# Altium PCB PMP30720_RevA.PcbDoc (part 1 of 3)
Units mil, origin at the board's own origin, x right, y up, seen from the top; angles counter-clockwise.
Board outline 4575 x 5400 mil, 4 copper layers (Top Layer, Signal Layer 1, Signal Layer 2, Bottom Layer), stack 61.6 mil thick; 223 components, 107 nets, 514 pads, 63 vias.
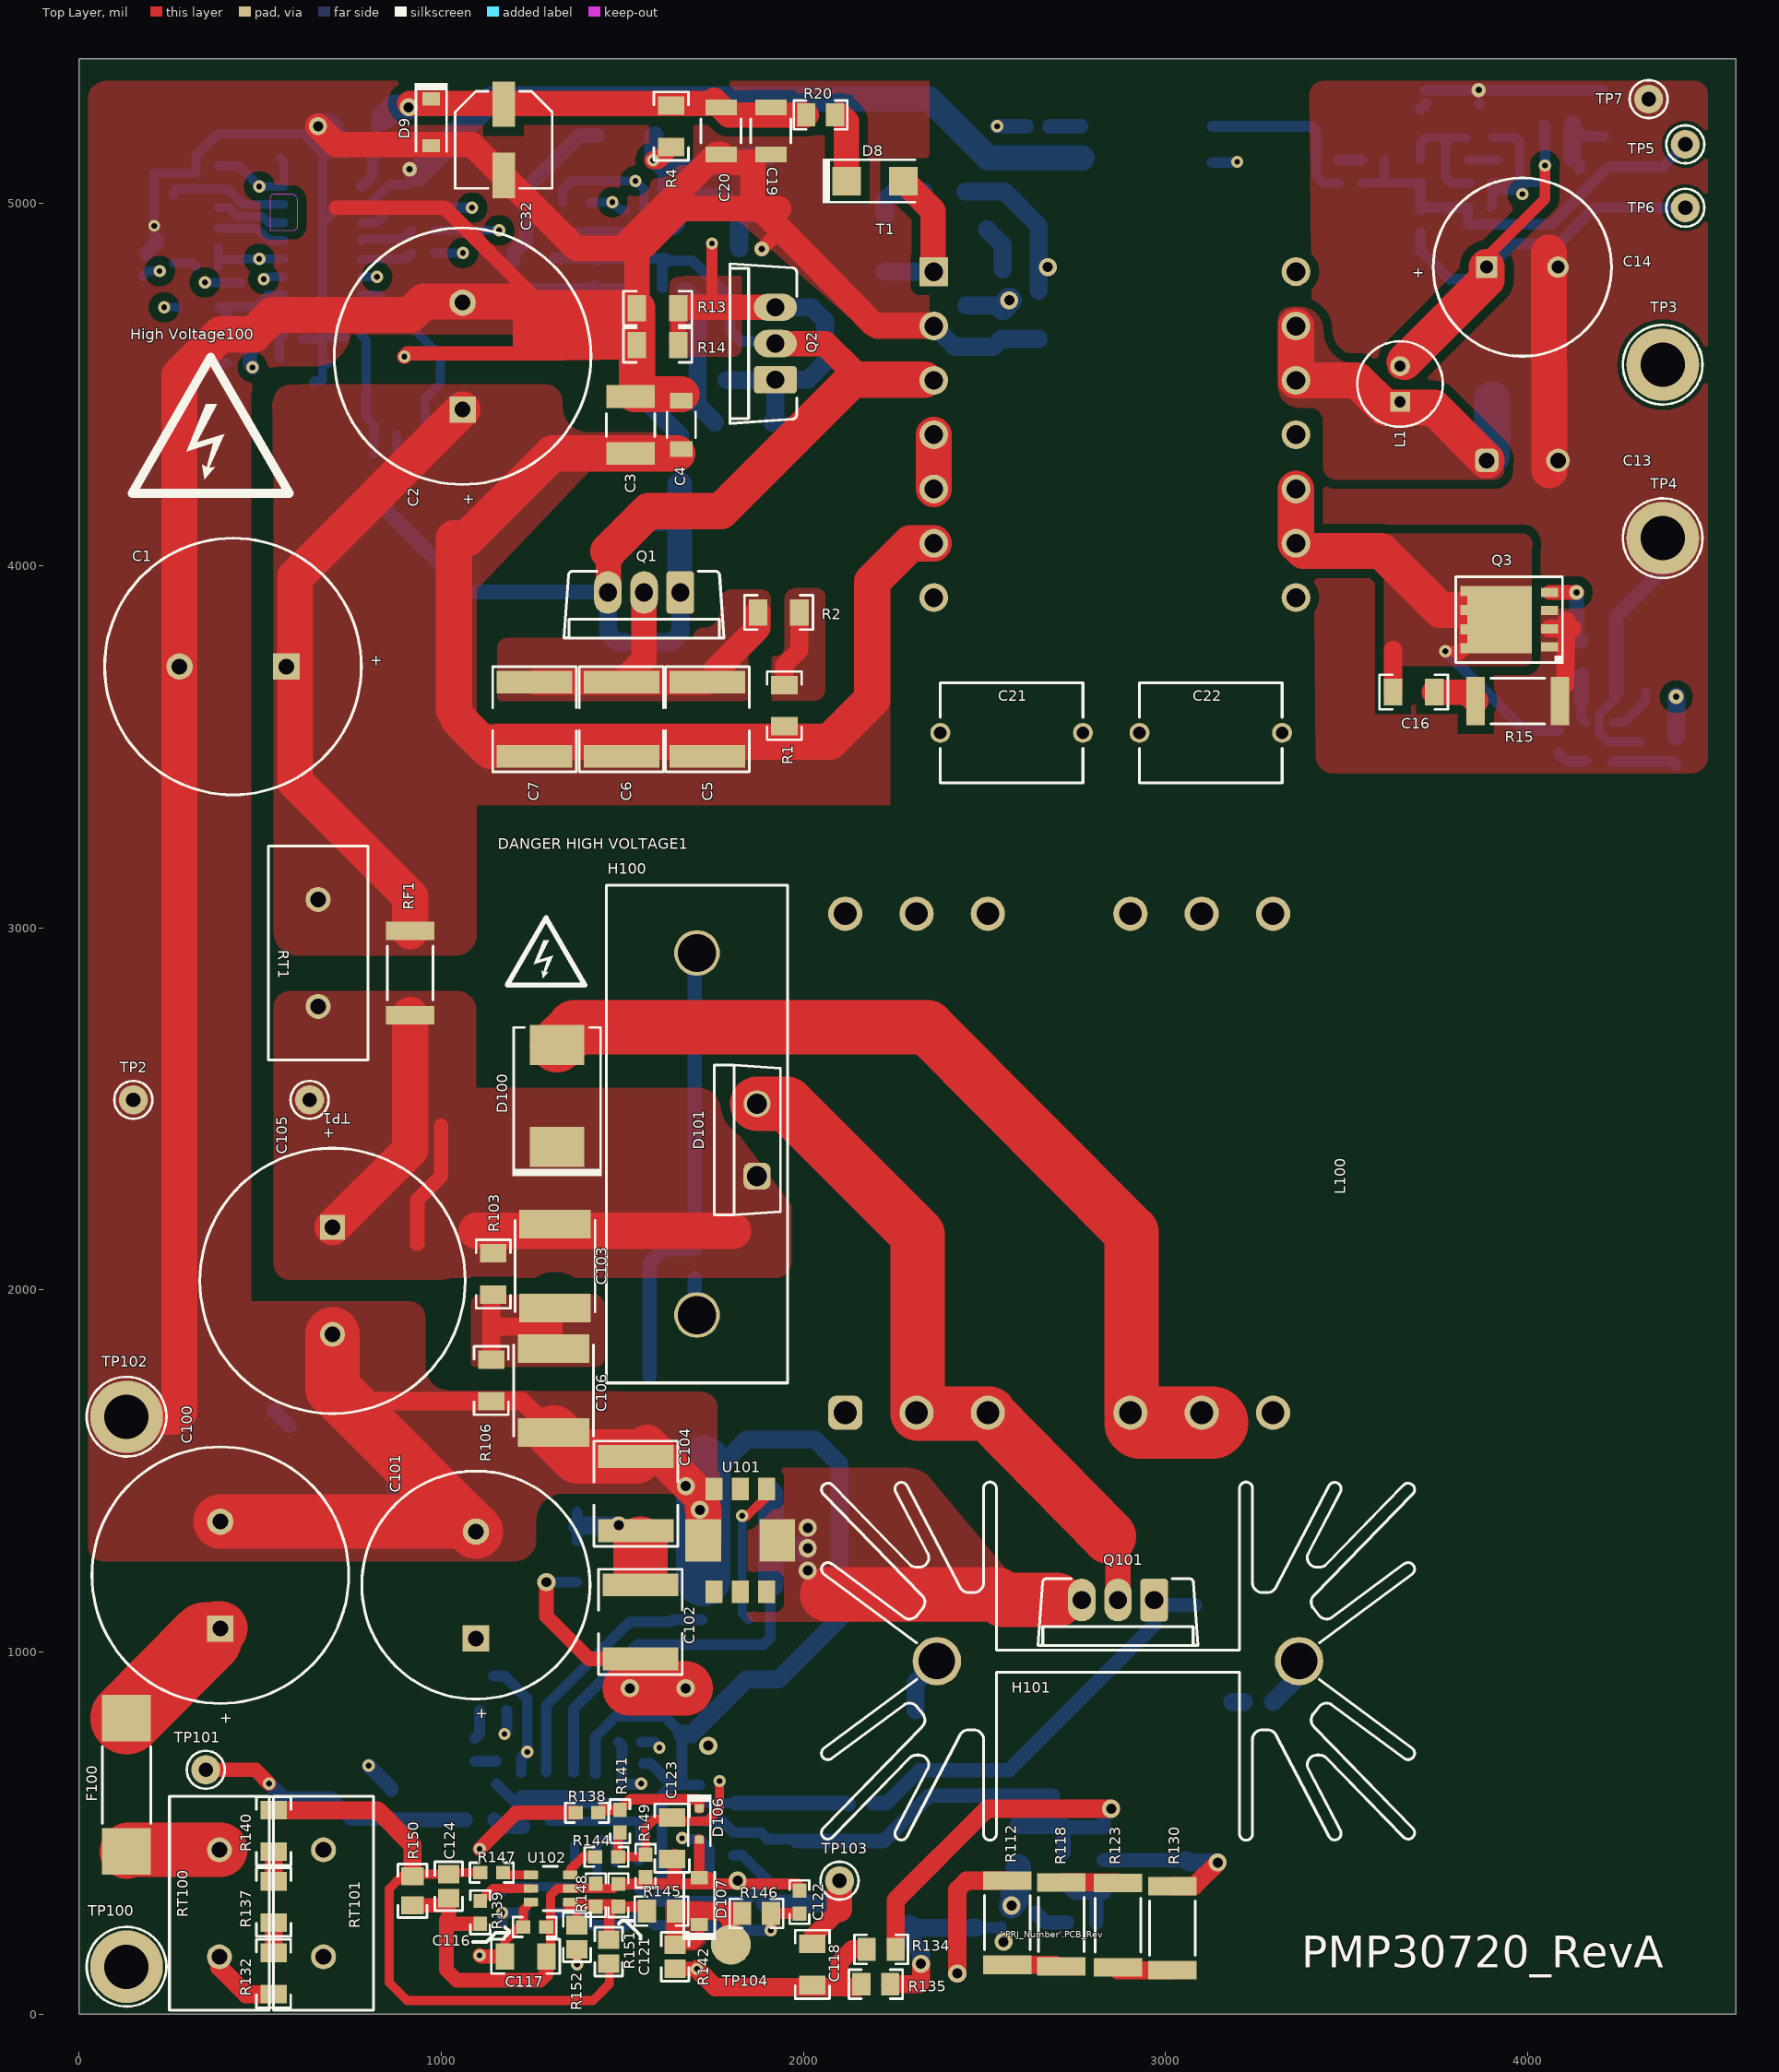
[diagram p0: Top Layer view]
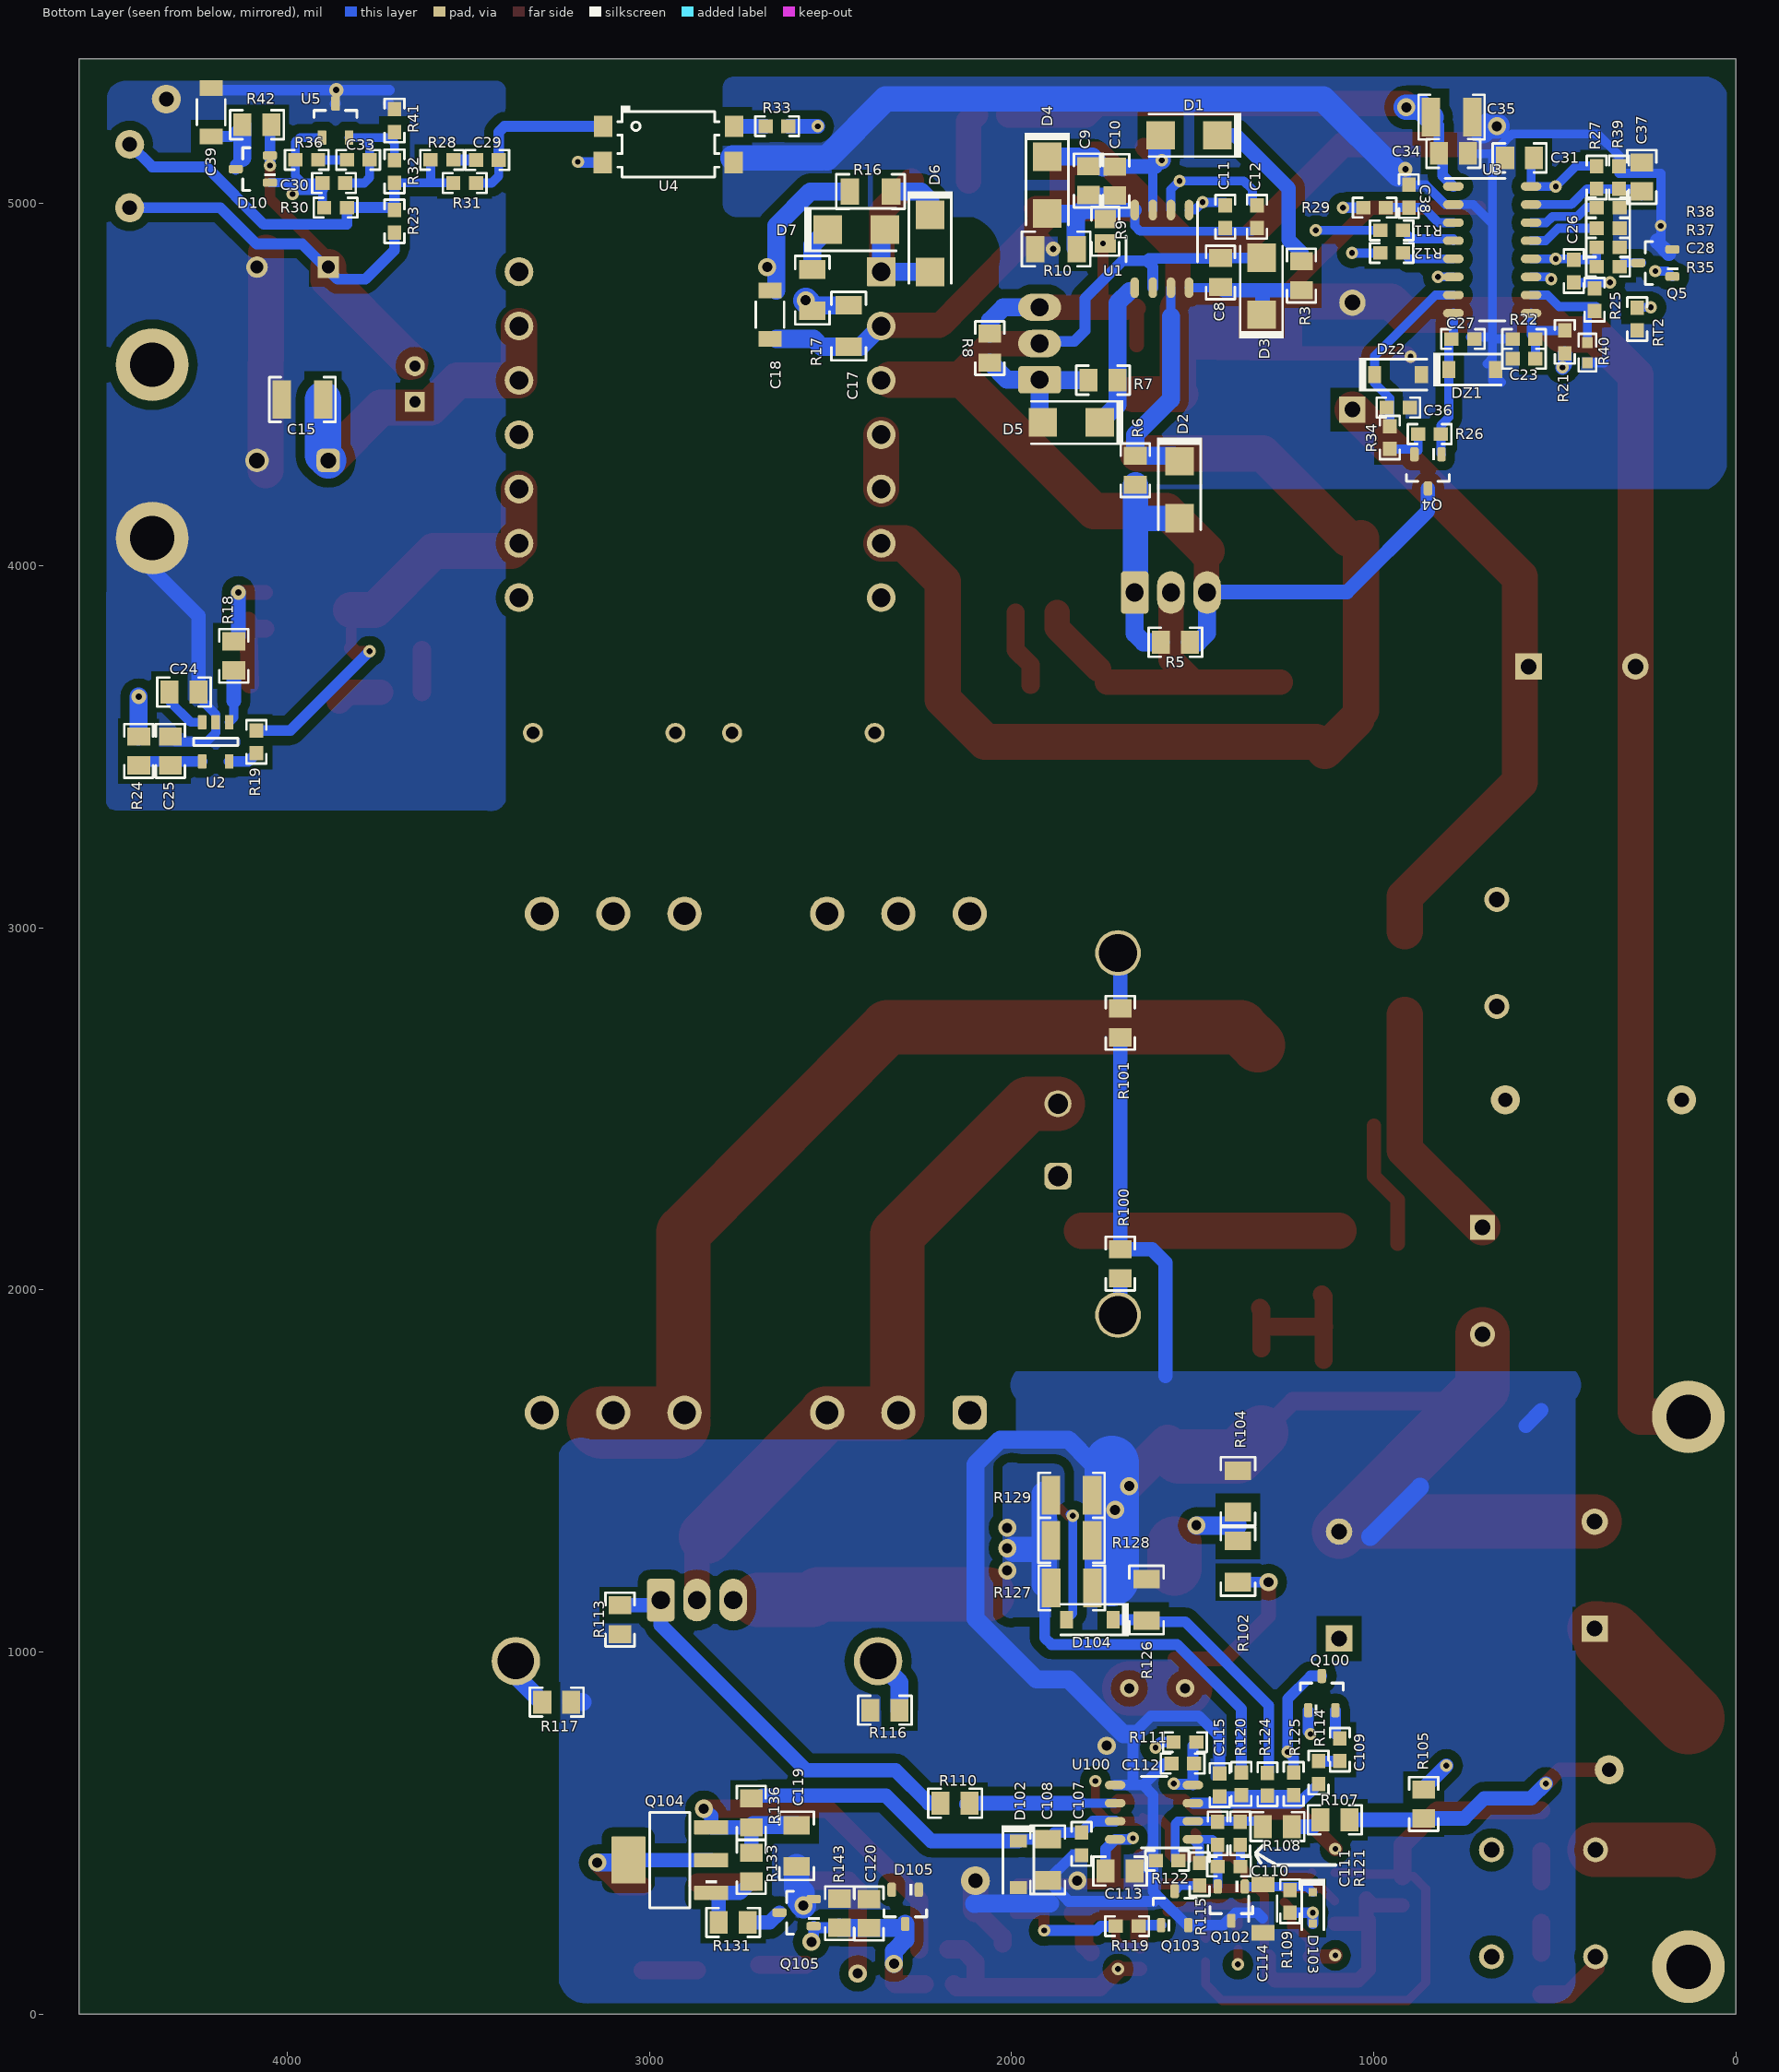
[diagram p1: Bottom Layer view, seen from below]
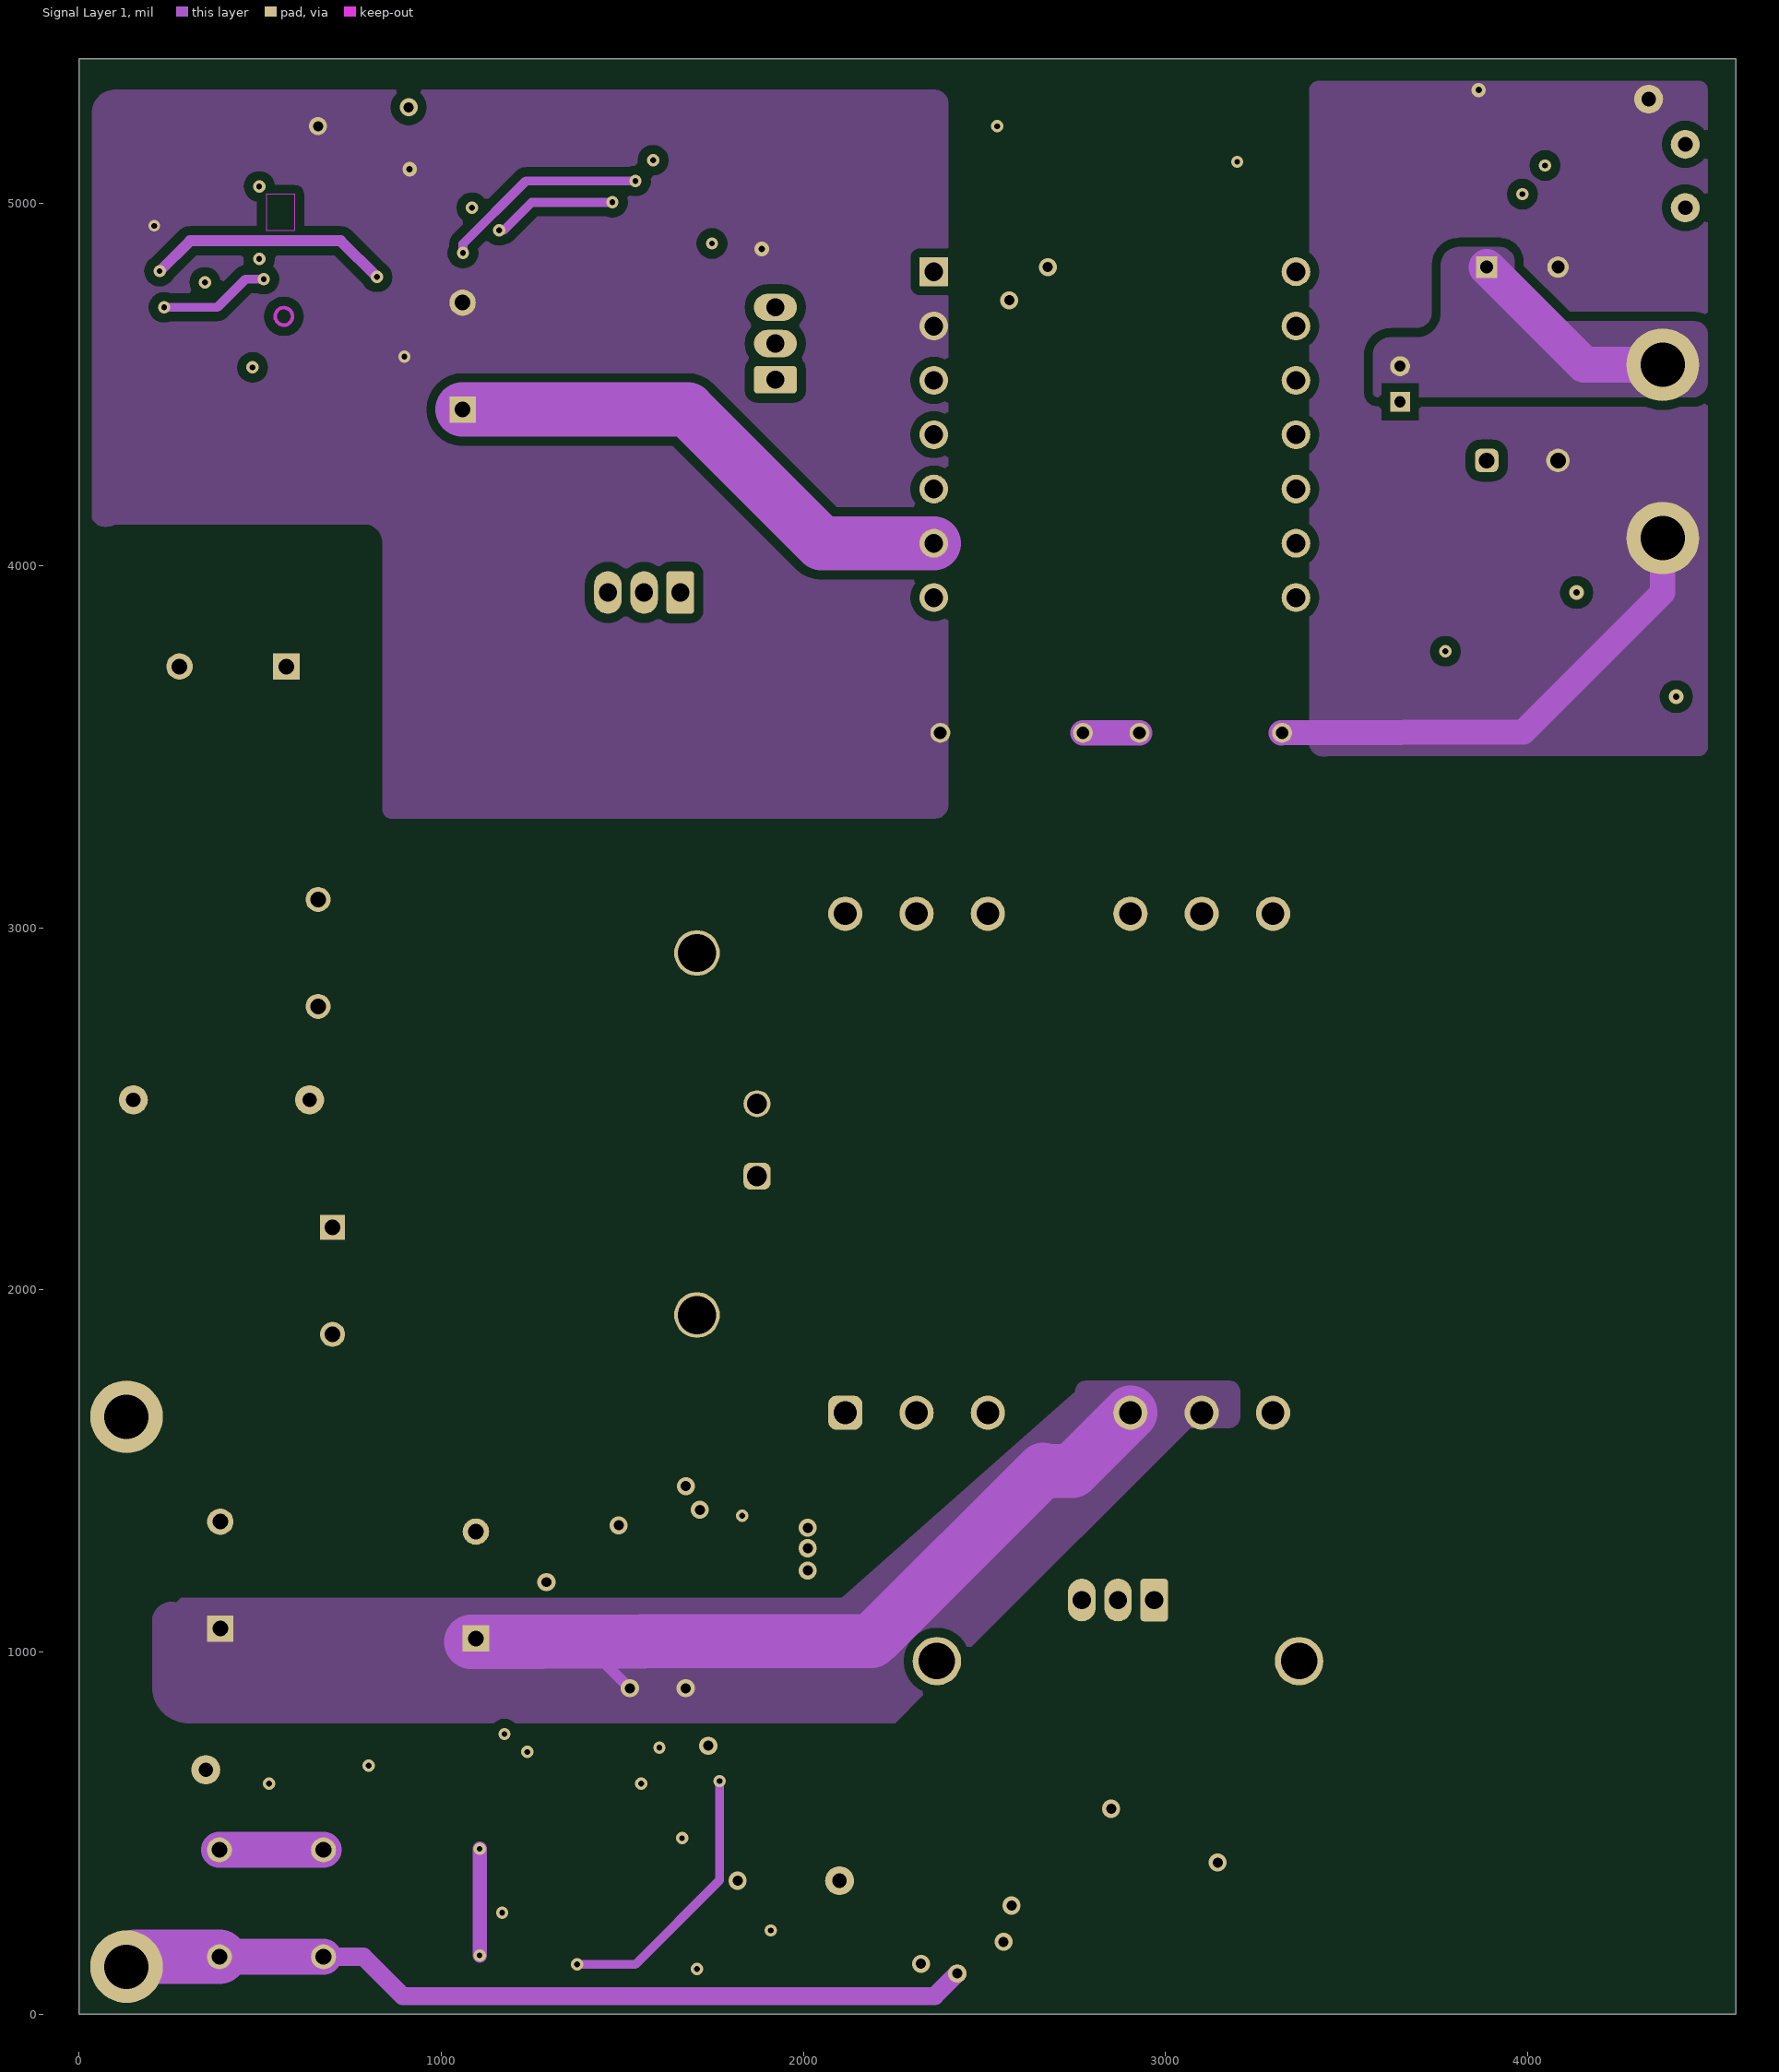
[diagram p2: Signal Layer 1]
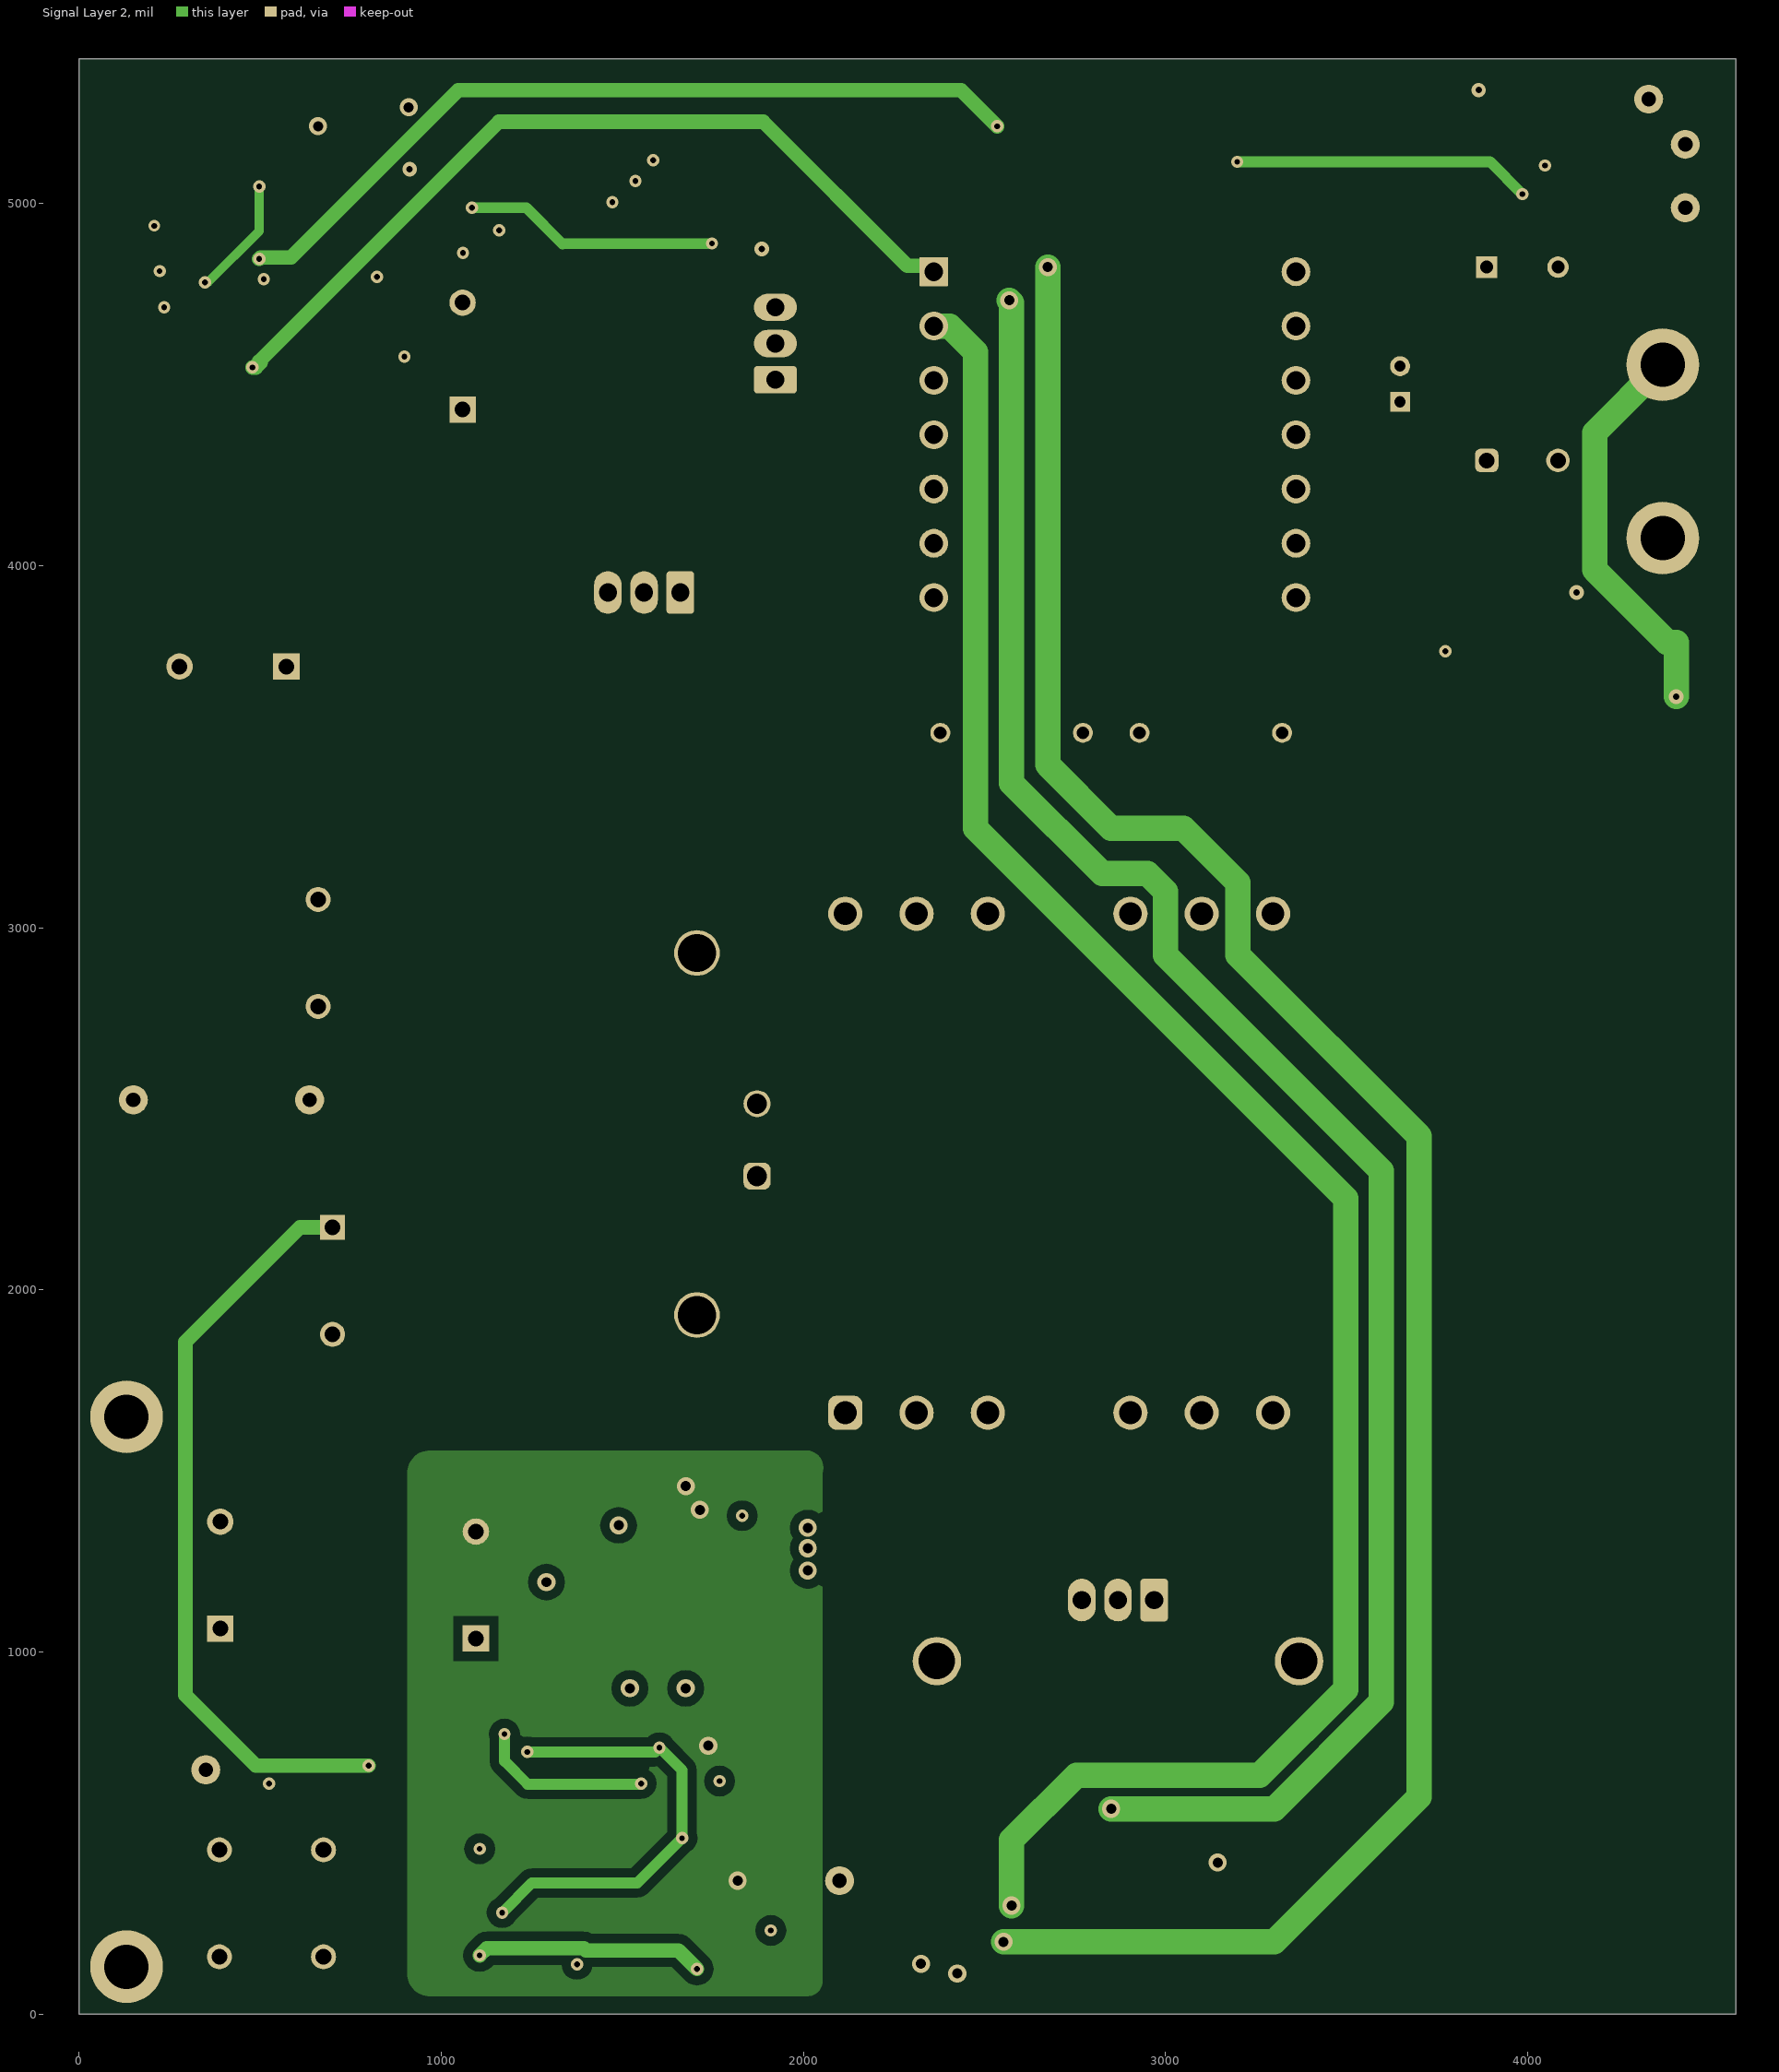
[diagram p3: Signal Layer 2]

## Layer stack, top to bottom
Top Solder: solder mask 0.4, Solder Resist, Dk 3.5
Top Layer: signal copper 1.4
Dielectric1: prepreg 8, FR-4, Dk 4.2
Signal Layer 1: signal copper 1.4
Dielectric 2: core 40, FR-4, Dk 4.2
Signal Layer 2: signal copper 1.4
Dielectric 3: prepreg 8, FR-4, Dk 4.2
Bottom Layer: signal copper 1.4
Bottom Solder: solder mask 0.4, Solder Resist, Dk 3.5

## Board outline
0,0 4575,0 4575,5400 0,5400

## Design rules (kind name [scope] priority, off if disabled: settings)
AcuteAngle [All] p1: minimum=4.50000000000000E+0001 checktracksonly=FALSE
AssemblyTestPointUsage [All] p1: valid=2
BoardOutlineClearance BoardOutlineClearance_MountingHoles [OnCopper and InComponentClass('Mounting Holes')] p1: gap=39.37 ignorepadtopadclearanceinfootprint=FALSE
BoardOutlineClearance BoardOutlineClearance_Poly [OnCopper and IsPoly] p2: gap=25 ignorepadtopadclearanceinfootprint=FALSE
BoardOutlineClearance [OnCopper and Not InComponentClass('Logo') and not InComponentClass('FiducialMark') and not InRegion(1000,500,4000,800) and not InPoly] p3: gap=18 ignorepadtopadclearanceinfootprint=FALSE
Clearance Clearance_Keepouts [((IsTrack Or IsArc) And Not InPoly) And IsFree and IsKeepOut vs ((IsTrack Or IsArc) And Not InPoly) And IsFree and IsKeepOut] p1: gap=0 ignorepadtopadclearanceinfootprint=FALSE
Clearance Clearance_Poly [InPolygon] p2: gap=25 ignorepadtopadclearanceinfootprint=TRUE
Clearance Clearance_FiducialMark [IsKeepOut and InComponentClass('FiducialMark') vs IsPad and InComponentClass('FiducialMark')] p3: gap=0 ignorepadtopadclearanceinfootprint=FALSE
Clearance [All] p4: gap=7.87 ignorepadtopadclearanceinfootprint=TRUE
ComponentClearance ComponentClearance_MountingHoles_FiducialMarks [InComponentClass('Mounting Holes') vs InComponentClass('FiducialMark')] p1: gap=50 collisioncheckmode=3 verticalgap=10 showdistances=FALSE
ComponentClearance ComponentClearance_Shunt [InComponentClass('Header') vs InComponentClass('Shunt')] p2: gap=0 collisioncheckmode=3 verticalgap=0 showdistances=FALSE
ComponentClearance ComponentClearance_Logo [InComponentClass('Logo')] p3: gap=50 collisioncheckmode=3 verticalgap=10 showdistances=FALSE
ComponentClearance ComponentClearance_ScrewToNut [(HasFootprint('NY PMS 440 0025 PH')) vs (HasFootprint('Keystone_1902C'))] p4: gap=5 collisioncheckmode=3 verticalgap=10 showdistances=FALSE
ComponentClearance ComponentClearance_MountingHoles [InComponentClass('Mounting Holes')] p5: gap=250 collisioncheckmode=3 verticalgap=100000 showdistances=FALSE
ComponentClearance ComponentClearance_SmallPassives [HasFootprint('0201*') or HasFootprint('0402*') or HasFootprint('0508') or HasFootprint('0603*') or HasFootprint('0612') or HasFootprint('0805*') or HasFootprint('0815*') or HasFootprint('0830*') or HasFootprint('1206*') or HasFootprint('1210*') or HasFootprint('1808*') or HasFootprint('1812*') or HasFootprint('1825*') or HasFootprint('2010*') or HasFootprint('2220*') or HasFootprint('2225*') or HasFootprint('2512*') or HasFootprint('2728*') or HasFootprint('3518*') vs HasFootprint('0201*') or HasFootprint('0402*') or HasFootprint('0508') or HasFootprint('0603*') or HasFootprint('0612') or HasFootprint('0805*') or HasFootprint('0815*') or HasFootprint('0830*') or HasFootprint('1206*') or HasFootprint('1210*') or HasFootprint('1808*') or HasFootprint('1812*') or HasFootprint('1825*') or HasFootprint('2010*') or HasFootprint('2220*') or HasFootprint('2225*') or HasFootprint('2512*') or HasFootprint('2728*') or HasFootprint('3518*')] p6: gap=14.96 collisioncheckmode=3 verticalgap=10 showdistances=FALSE
ComponentClearance ComponentClearance_THtoSMT [IsThruComponent vs IsSMTComponent] p7: gap=10 collisioncheckmode=3 verticalgap=10 showdistances=FALSE
ComponentClearance ComponentClearance_THtoTH [IsThruComponent vs IsThruComponent] p8: gap=10 collisioncheckmode=3 verticalgap=10 showdistances=FALSE
ComponentClearance [All] p9: gap=0 collisioncheckmode=3 verticalgap=0 showdistances=FALSE
DiffPairsRouting [All] p1: maxlimit=100 minlimit=10 mostfreqgap=10 toplayer_minwidth=15 toplayer_maxwidth=15 toplayer_prefwidth=15 midlayer1_minwidth=15 midlayer1_maxwidth=15 midlayer1_prefwidth=15 midlayer2_minwidth=15 midlayer2_maxwidth=15 midlayer2_prefwidth=15 bottomlayer_minwidth=15 bottomlayer_maxwidth=15 bottomlayer_prefwidth=15 maxuncoupledlength=1000
FabricationTestPointUsage TestPointUsage [All] p1: valid=2 allowmultiple=FALSE
FabricationTestpoint Testpoint [All] p1: side=3 testpointundercomponent=TRUE minsize=40 maxsize=100 preferedsize=60 minholesize=0 maxholesize=40 preferedholesize=32 testpointgrid=1 allowsidetop=TRUE allowsidebottom=TRUE usegrid=TRUE gridtolerance=0.01
FanoutControl Fanout_LCC [IsLCC] p1: bgadir=Out bgaviamode=Centered fanoutstyle=Auto fanoutdirection=Alternating viagrid=1 // Fanout_LCC (Default Rule)
FanoutControl Fanout_BGA [IsBGA] p2: bgadir=Out bgaviamode=Centered fanoutstyle=Auto fanoutdirection=Alternating viagrid=1 // Fanout_BGA (Default Rule)
FanoutControl Fanout_Default [All] p4: bgadir=Out bgaviamode=Centered fanoutstyle=Auto fanoutdirection=Alternating viagrid=1 // Fanout_Default (Default Rule)
FanoutControl Fanout_Small [(CompPinCount < 5)] p5: bgadir=Out bgaviamode=Centered fanoutstyle=Auto fanoutdirection=OutThenIn viagrid=1 // Fanout_Small (Default Rule)
Height [All] p1: minheight=0 maxheight=4000 prefheight=500
HoleSize [All] p1: absolutevalues=TRUE maxlimit=251 minlimit=7.87 maxpercent=80.000 minpercent=20.000
MinimumAnnularRing MinimumAnnularRing_ThermalPadVias [IsVia and InAnyComponent] p1: minimumring=5.91
MinimumAnnularRing [All] p2: minimumring=7.87
MinimumSolderMaskSliver MinimumSolderMaskSliver_Logo [InComponentClass('Logo') vs InComponentClass('Logo')] p1: minsoldermaskwidth=0.7
MinimumSolderMaskSliver [All] p2: minsoldermaskwidth=1
PlaneConnect [All] p1: planeconnectstyle=Relief reliefexpansion=10 reliefentries=4 reliefconductorwidth=10 reliefairgap=10
PolygonConnect [All] p1: connectstyle=Direct reliefconductorwidth=10 reliefentries=4 polygonreliefangle="90 Angle" airgapwidth=10
RoutingVias ThermalPadVias [IsVia and InAnyComponent] p1: holewidth=7.87 width=19.68 viastyle="Through Hole" minholewidth=7.87 minwidth=19.68 maxholewidth=12.99 maxwidth=23.62
RoutingVias [All] p2: holewidth=16 width=34 viastyle="Through Hole" minholewidth=7.87 minwidth=26 maxholewidth=40 maxwidth=65
SilkToBoardRegionClearance [Not ((IsComment or IsDesignator) And (Hide <> 'False')) and not InRegion(1000,500,4000,800)] p1:
SilkToSilkClearance SilkToSilkClearance_Pb-FreeLogo [(HasFootprint('Pb-Free_Overlay_Medium') OR HasFootprint('Pb-Free_Overlay_Small')) vs (HasFootprint('Pb-Free_Overlay_Medium') OR HasFootprint('Pb-Free_Overlay_Small'))] p1 off: silktosilkclearance=0
SilkToSilkClearance [All] p2 off: silktosilkclearance=3.94
SilkToSolderMaskClearance SilkToComponentPadClearance [(IsPad or IsFill or IsRegion) and InAnycomponent] p1 off: minsilkscreentomaskgap=5 clearancetoexposedcopper=TRUE
SilkToSolderMaskClearance "Silk to Solder Mask Opening" [All] p2 off: minsilkscreentomaskgap=3.94 clearancetoexposedcopper=FALSE
SolderMaskExpansion [All] p1: expansion=1.97
UnRoutedNet [All] p1: checkbadconnections=TRUE
Width [All] p1: maxlimit=200 minlimit=6 preferedwidth=20 midlayer1_prefwidth=10 midlayer2_prefwidth=10 minimp=50.000000 maximp=50.000000 favimp=50.000000 checkconnectedcopper=TRUE
13 further rules are at their usual default settings.

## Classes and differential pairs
component class "PMP30720_RevA ACF": C1 C2 C3 C4 C5 C6 C7 C8 C9 C10 C11 C12 C13 C14 C15 C16 C17 C18 C19 C20 C21 C22 C23 C24 C25 C26 C27 C28 C29 C30 C31 C32 C33 C34 C35 C36 C37 C38 C39 D1 D2 D3 D4 D5 D6 D7 D8 D9 D10 "DANGER HIGH VOLTAGE1" DZ1 Dz2 L1 Q1 Q2 Q3 Q4 Q5 R1 R2 R3 R4 R5 R6 R7 R8 R9 R10 R11 R12 R13 R14 R15 R16 R17 R18 R19 R20 R21 R22 R23 R24 R25 R26 R27 R28 R29 R30 R31 R32 R33 R34 R35 R36 R37 R38 R39 R40 R41 R42 RF1 RT1 RT2 T1 TP1 TP2 TP3 TP4 TP5 TP6 TP7 U1 U2 U3 U4 U5
component class "PMP30720_RevA DCDC": C100 C101 C102 C103 C104 C105 C106 C107 C108 C109 C110 C111 C112 C113 C114 C115 C116 C117 C119 C120 C121 C122 C123 C124 D100 D101 D102 D103 D104 D105 D106 D107 F100 H100 H101 "High Voltage100" L100 Q100 Q101 Q102 Q103 Q104 Q105 R100 R101 R102 R103 R104 R105 R106 R107 R108 R109 R110 R111 R112 R113 R114 R115 R116 R117 R118 R119 R120 R121 R122 R123 R124 R125 R126 R127 R128 R129 R130 R131 R132 R133 R134 R135 R136 R137 R138 R139 R140 R141 R142 R143 R144 R145 R146 R147 R148 R149 R150 R151 R152 R? RT100 RT101 TP100 TP101 TP102 TP103 TP104 TP? U100 U101 U102

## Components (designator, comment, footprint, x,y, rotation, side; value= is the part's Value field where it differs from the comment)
C1 "450BXW82MEFR18X30" CAPPR7.5-18x31.5 425,3721.58 r180 top value=DNP
C2 "450BXW82MEFR18X30" CAPPR7.5-18x31.5 1059.04,4578.68 r90 top value=82uF
C3 "1812Y5000474KXTWS2" 1812_254 1522.64,4388.47 r90 top value=0.47uF
C4 "C3216X7T2W104K160AA" 1206_190 1663.32,4388.47 r90 top value=0.1uF
C5 "GRM55DR72E474KW01L" 2220 1735.14,3575.97 r90 top value=0.47uF
C6 "DNP" 2220 1497.64,3575.97 r90 top value=0.68uF
C7 "GRM55DR72E684KW01L" 2220 1257.95,3575.97 r90 top value=DNP
C8 "C0805C154K5RACTU" 0805_HV 1423.29,4809.51 r90 bottom value=0.15uF
C9 "GRM21BR71H105KA12L" 0805_HV 1787.64,5063.47 r270 bottom value=1uF
C10 "GRM21BR71H104KA01L" 0805_HV 1715.04,5062.28 r270 bottom value=0.1uF
C11 "GRM1885C1H330JA01D" 0603 1410.14,4963.47 r270 bottom value=33pF
C12 "GRM1885C1H330JA01D" 0603 1322.64,4963.47 r270 bottom value=33pF
C13 "EEU-FM1V122L" Panasonic_1250x3000 3985.14,4290.63 r0 top value=1200uF
C14 "DNP" CAPPR5-12.5x25 3985.14,4824.48 r0 top
C15 "GRM32ER71H106KA12L" 1210_270 3958.18,4458.79 r0 bottom value=10uF
C16 "GRM31BR72J152KW01L" 1206 3685.14,3650.97 r180 top value=1500pF
C17 "GRM31MR71H105KA88L" 1206 2450,4661.78 r270 bottom value=1uF
C18 "C3216X7R1H155K160AB" 1206_180 2667.05,4693.21 r270 bottom value=1.5uF
C19 "C3225X7R1H106M250AC" 1210_280 1910.14,5200.97 r270 top value=10uF
C20 "C3225X7R1H106M250AC" 1210_280 1772.64,5200.97 r270 top value=10uF
C21 "SHORT" KX_1000x700 2575,3538.47 r180 top
C22 "DE1E3KX332MN4AP01F" KX_1000x700 3125,3538.47 r180 top value=3300pF
C23 "06035A3R3CAT2A" 0603 585.14,4571.5 r0 bottom value=3.3pF
C24 "C2012X7R1H225K125AC" 0805_HV 4285.14,3650.97 r180 bottom value=2.2uF
C25 "GRM21BR71H105KA12L" 0805_HV 4322.64,3488.47 r90 bottom value=1uF
C26 "GRM1885C1H101JA01D" 0603 447.64,4813.47 r270 bottom value=100pF
C27 "GRM188R71H222KA01D" 0603 753.93,4625.97 r0 bottom value=2200pF
C28 "GRM188R71H153KA01D" 0603 353.12,4878.77 r180 bottom value=0.015uF
C29 "GRM188R71H153KA01D" 0603 3447.64,5120.22 r180 bottom value=0.015uF
C30 "06035A3R3CAT2A" 0603 3871.13,5056.78 r0 bottom value=3.3pF
C31 "GRM21BR71H104KA01L" 0805_HV 597.64,5125.97 r0 bottom value=0.1uF
C32 "EEE-FK1V101XP" SM_RADIAL_D8 1172.64,5175.97 r270 top value=100uF
C33 "GRM188R71H332KA01D" 0603 3804.13,5120.63 r0 bottom value=3300pF
C34 "GRM21BR71H104KA01L" 0805_HV 780.27,5138.47 r180 bottom value=0.1uF
C35 "GRM32ER71H106MA12" 1210_270 785.14,5238.47 r180 bottom value=10uF
C36 "GRM1885C1H270JA01D" 0603 932.38,4436.63 r180 bottom value=27pF
C37 "GRM2165C1H181JA01D" 0805_HV 260.14,5073.59 r90 bottom value=180pF
C38 "GRM1885C1H270JA01D" 0603 903.09,5020.41 r90 bottom value=27pF
C39 "GRM31CR71H225KA88L" 1206_180 4210.14,5252.44 r90 bottom value=2.2uF
C100 "TBD" CAPPR7.5-18x20 390.18,1212.5 r90 top
C101 "UVK2W470MHD" CAPPR7.5-16x31.5 1095.87,1185.04 r90 top value=47uF
C102 "DNP" 2220 1550,1083.43 r90 top
C103 "CKG57NX7R2E225M500JH" CKG57N 1314.45,2066.11 r270 top value=2.2uF
C104 "DNP" 2220 1537.5,1437.5 r90 top
C105 "EEU-EE2G470S" EE_1800x2000 700,2025 r270 top value=47uF
C106 "CKG57NX7R2E225M500JH" CKG57N 1310.28,1722.39 r270 top value=2.2uF
C107 "GCM188R71H104KA57D" 0603 1806.82,470.3 r270 bottom value=0.1uF
C108 "GRM31MR71E225KA93L" 1206 1900.57,426.55 r270 bottom value=2.2uF
C109 "SHORT" 0603 1093.53,730.52 r90 bottom
C110 "C1608X7R1H474K080AC" 0603 1399.78,407.95 r180 bottom value=0.47uF
C111 "GRM1885C1H470JA01D" 0603 1431.03,499.27 r90 bottom value=47pF
C112 "GRM1885C1H471JA01D" 0603 1527.61,692.4 r0 bottom value=470pF
C113 "GRM21BR71C105KA01L" 0805_HV 1700.57,395.3 r180 bottom value=1uF
C114 "GRM31CR71E475KA88L" 1206_180 1306.03,291.48 r270 bottom value=4.7uF
C115 "GRM1885C1H101JA01D" 0603 1425.57,632.8 r90 bottom value=100pF
C116 "GRM188R71H104KA93D" 0603 1258.12,240.94 r0 top value=0.1uF
C117 "GRM31MR71H105KA88L" 1206 1233.12,159.69 r0 top value=1uF
C118 "GRM31MR71H105KA88L" 1206 2025,137.5 r90 top value=1uF
C119 "GRM31MR71H105KA88L" 1206 2593.75,464.97 r270 bottom value=1uF
C120 "GRM21BR71H224KA01L" 0805_HV 2393.75,277.96 r90 bottom value=0.22uF
C121 "Used in BOM report" 0603 1489.37,328.44 r90 top value=DNP
C122 "GRM1885C1H101JA01D" 0603 1989.37,309.69 r90 top value=100pF
C123 "GRM31MR71H105KA88L" 1206 1637.5,486.15 r270 top value=1uF
C124 "DNP" 0805 1020.62,353.44 r270 top
D1 "MURA160T3G" SMA 1510.14,5188.47 r0 bottom value=600V
D2 "B130-13-F" SMA 1536.32,4209.5 r270 bottom value=30V
D3 "SMAZ18-13-F" SMA 1310.14,4771.95 r90 bottom value=18V
D4 "SMAZ18-13-F" SMA 1901.58,5050.97 r270 bottom value=18V
D5 "B130-13-F" SMA 1835.14,4395.36 r0 bottom value=30V
D6 "ES1D-13-F" SMA 2225,4889.98 r270 bottom value=200V
D7 "ES1D-13-F" SMA 2428.94,4928.2 r180 bottom value=200V
D8 "SS1200-LTP" SMA 2197.64,5062.28 r0 top value=200V
D9 "MMSZ5254B-7-F" SOD-123 972.64,5224.57 r270 top value=27V
D10 "BAT54S-7-F" SOT-23 4095.13,5095.06 r0 bottom value=30V
D100 "RS3K-E3/9AT" SMC 1319.95,2535.77 r90 top value=800V
D101 "STPSC1006D" TO-220-2 1872.22,2414.25 r90 top value=600V
D102 "MMSZ5248B-7-F" SOD-123 1981.25,413.85 r270 bottom value=18V
D103 "BAT54HT1G" SOD-323 1168.53,293.46 r270 bottom value=30V
D104 "MBR0520LT1G" SOD-123 1783.86,1089.68 r0 bottom value=20V
D105 "MMBZ5248BLT1G" SOT-23 2293.75,296.37 r270 bottom value=18V
D106 "MMSZ5240BS-7-F" SOD-323 1712.5,525.32 r270 top value=10V
D107 "MMSZ4688T1G" SOD-123 1712.5,312.5 r90 top value=4.7V
"DANGER HIGH VOLTAGE1" "DANGER HIGH VOLTAGE" IEC_HighVoltage_Small 1289.62,2930.14 r0 top
DZ1 "MMSZ5252B-7-F" SOD-123 728.05,4541.77 r180 bottom value=24V
Dz2 "MMSZ5248B-7-F" SOD-123 933.17,4527.8 r180 bottom value=18V
F100 "0443005.DR" FUSE_0443 131.25,633.43 r270 top
H100 "531002B02500G" HSINK_531002B02500G 1706.25,2430.7 r270 top
H101 "FA-T220-64E" HSINK_FA-T220-64E 2868.75,975 r0 top
"High Voltage100" "DANGER HIGH VOLTAGE" IEC_HighVoltage_Medium 363.44,4375 r0 top
L1 "7447462010" WE-TI_5075 3647.64,4501.75 r90 top value=1uH
L100 "750318149" 750318149 2706.25,2350 r90 top value=300uH
Q1 "IPAW60R360P7SXKSA1-ND" TO-220AB 1560.14,3925.97 r180 top
Q2 "IPAW60R360P7SXKSA1-ND" TO-220AB 1922.64,4613.47 r90 top
Q3 "SiR616" PG-TDSON-8 3948.8,3850.97 r180 top value=200V
Q4 "BSS126 H6906" SOT-23 850.48,4260.32 r270 bottom value=600V
Q5 "2N7002-7-F" SOT-23 222.64,4836.01 r0 bottom value=60V
Q100 "MMBT3904-7-F" SOT-23 1143.53,886.77 r90 bottom value="40 V"
Q101 "IPP60R125CFD7" TO-220AB 2868.75,1143.75 r180 top value=600V
Q102 "MMBT2907ALT1G" SOT-23 1393.53,305.3 r270 bottom value="60 V"
Q103 "MMBT3904-7-F" SOT-23 1549.78,293.02 r90 bottom value="40 V"
Q104 "CPC3960ZTR" SOT-223 2943.75,425.58 r0 bottom value=600V
Q105 "2N7002-7-F" SOT-23 2593.75,280.52 r0 bottom value=60V
R1 "CRCW1206383KFKEA" 1206 1947.64,3613.47 r270 top value=383k
R2 "CRCW1206383KFKEA" 1206 1931.9,3870.92 r0 top value=383k
R3 "CRCW080510R0JNEA" 0805_HV 1199.81,4800.97 r90 bottom value=10
R4 "CRCW1206100RJNEA" 1206 1635.14,5213.47 r270 top value=100
R5 "CRCW08054K99FKEA" 0805_HV 1547.64,3788.47 r0 bottom value=4.99k
R6 "CRCW080515R0FKEA" 0805_HV 1658.54,4263.47 r90 bottom value=15.0
R7 "CRCW080515R0FKEA" 0805_HV 1747.64,4512.54 r180 bottom value=15.0
R8 "CRCW08054K99FKEA" 0805_HV 2060.14,4600.97 r270 bottom value=4.99k
R9 "DNP" 0805 1741.21,4923.47 r270 bottom
R10 "CRCW12060000Z0EA" 1206 1877.36,4874.43 r180 bottom value=0
R11 "CRCW060349R9FKEA" 0603 950.71,4925.97 r0 bottom value=49.9
R12 "CRCW060349R9FKEA" 0603 950.71,4863.47 r0 bottom value=49.9
R13 "ERJ-8RQFR27V" 1206 1597.64,4710.77 r0 top value=0.27
R14 "ERJ-8RQFR33V" 1206 1597.64,4609.19 r0 top value=0.33
R15 "CRCW25123R30JNEG" 2512 3972.64,3625.97 r0 top value=3.3
R16 "CRCW1206499RFKEA" 1206 2389.78,5033.09 r180 bottom value=499
R17 "CRCW120610R0FKEA" 1206 2550,4760.97 r90 bottom value=10.0
R18 "CRCW080510R0FKEA" 0805_HV 4147.64,3750.97 r90 bottom value=10.0
R19 "CRCW060310R0FKEA" 0603 4085.14,3513.47 r90 bottom value=10.0
R20 "CRCW080510R0JNEA" 0805_HV 2047.64,5244.86 r0 top value=10
R21 "CRCW060341K2FKEA" 0603 472.64,4617.95 r270 bottom value=41.2k
R22 "CRCW060310K0FKEA" 0603 585.14,4625.97 r180 bottom value=10.0k
R23 "CRCW060349R9FKEA" 0603 3704.13,4950.97 r270 bottom value=49.9
R24 "CRCW080510R0JNEA" 0805_HV 4410.14,3488.47 r90 bottom value=10
R25 "CRCW06030000Z0EA" 0603 390.4,4734.65 r270 bottom value=0
R26 "CRCW06031M00FKEA" 0603 845.99,4363.47 r180 bottom value=1.00Meg
R27 "CRCW0603196KFKEA" 0603 385.14,5071.97 r270 bottom value=196k
R28 "CRCW06031K00FKEA" 0603 3572.64,5120.63 r0 bottom value=1.00k
R29 "CRCW06031K00FKEA" 0603 997.64,4988.91 r180 bottom value=1.00k
R30 "CRCW060334K0FKEA" 0603 3866.63,4988.91 r180 bottom value=34.0k
R31 "RC0603FR-0712K1L" 0603 3510.14,5056.78 r0 bottom value=12.1k
R32 "CRCW0603150KFKEA" 0603 3704.13,5088.73 r270 bottom value=150k
R33 "CRCW060315K0FKEA" 0603 2647.64,5213.47 r180 bottom value=15.0k
R34 "CRCW0603121RFKEA" 0603 955.76,4353.9 r270 bottom value=121
R35 "CRCW0603604KFKEA" 0603 353.12,4825.97 r0 bottom value=604k
R36 "CRCW0603150KFKEA" 0603 3946.13,5120.63 r180 bottom value=150k
R37 "CRCW0603249KFKEA" 0603 353.12,4931.97 r0 bottom value=249k
R38 "CRCW0603124KFKEA" 0603 353.12,4988.91 r0 bottom value=124k
R39 "CRCW060347K5FKEA" 0603 323.14,5071.97 r270 bottom value=47.5k
R40 "DNP" 0603_HV 410.14,4588.47 r270 bottom
R41 "CRCW060321K5FKEA" 0603 3704.13,5229.03 r270 bottom value=21.5k
R42 "CRCW0805100KFKEA" 0805_HV 4083.71,5217.77 r0 bottom value=100k
R100 "CRCW08050000Z0EA" 0805_HV 1700,2072.5 r270 bottom value=0
R101 "CRCW08050000Z0EA" 0805_HV 1700,2737.5 r90 bottom value=0
R102 "DNP" 1206 1375,1250.28 r270 bottom
R103 "CRCW1206499KFKEA" 1206 1143.75,2044.06 r90 top value=499k
R104 "DNP" 1206 1375,1443.75 r270 bottom
R105 "CRCW080549R9FKEA" 0805_HV 862.28,580.52 r90 bottom value=49.9
R106 "CRCW1206499KFKEA" 1206 1138.09,1750 r90 top value=499k
R107 "CRCW0805374KFKEA" 0805_HV 1107.51,536.77 r180 bottom value=374k
R108 "CRCW0805374KFKEA" 0805_HV 1266.06,518.02 r180 bottom value=374k
R109 "CRCW060310K0FKEA" 0603 1231.03,311.77 r270 bottom value=10.0k
R110 "CRCW080510R0JNEA" 0805_HV 2156.03,582.8 r0 bottom value=10
R111 "CRCW060330K1FKEA" 0603 1521.36,751.15 r0 bottom value=30.1k
R112 "CRCW25124K70JNEG" 2512 2563.36,252.71 r90 top value=4.7k
R113 "CRCW080510K0FKEA" 0805_HV 3081.25,1089.68 r90 bottom value=DNP
R114 "CRCW06036K98FKEA" 0603 1152.61,667.4 r270 bottom value=6.98k
R115 "CRCW06030000Z0EA" 0603 1481.03,386.77 r90 bottom value=0
R116 "CRCW08050000Z0EA" 0805_HV 2349.78,839.52 r180 bottom value=0
R117 "CRCW08050000Z0EA" 0805_HV 3256.03,861.77 r0 bottom value=0
R118 "CRCW25124K70JNEG" 2512 2712.5,248.03 r270 top value=4.7k
R119 "CRCW06030000Z0EA" 0603 1681.03,243.02 r0 bottom value=0
R120 "DNP" 0603 1365.57,635.9 r90 bottom
R121 "CRCW0603249KFKEA" 0603 1368.53,499.27 r270 bottom value=249k
R122 "CRCW060319K1FKEA" 0603 1570.82,424.27 r180 bottom value=19.1k
R123 "CRCW25124K70JNEG" 2512 2868.75,245.96 r90 top value=4.7k
R124 "CRCW06032K21FKEA" 0603 1293.53,634.92 r90 bottom value=2.21k
R125 "DNP" 0603 1221.36,635.9 r270 bottom
R126 "CRCW12064R99FKEA" 1206 1627.61,1144.08 r270 bottom value=4.99
R127 "DNP" 1210 1833.86,1177.18 r0 bottom
R128 "DNP" 1210 1834.72,1308.43 r0 bottom
R129 "DNP" 1210 1834.72,1433.43 r0 bottom
R130 "CRCW25124K70JNEG" 2512 3018.75,237.5 r270 top value=4.7k
R131 "CRCW0805200KJNEA" 0805_HV 2768.75,253.31 r180 bottom value=200k
R132 "CRCW12060000Z0EA" 1206 537.2,112.5 r270 top value=0
R133 "CRCW0805200KJNEA" 0805_HV 2718.75,406.25 r270 bottom value=200k
R134 "CRCW08050000Z0EA" 0805_HV 2215,179.04 r0 top value=0
R135 "DNP" 0805_HV 2200,83.12 r0 top
R136 "CRCW08050000Z0EAHP" 0805_HV 2718.75,556.25 r270 bottom value=0
R137 "CRCW12063M92FKEA" 1206 537.5,309.79 r270 top value=3.92Meg
R138 "CRCW0603249KFKEA" 0603 1402.48,556.25 r180 top value=249k
R139 "Used in BOM report" 0603 1107.87,281.25 r90 top value=DNP
R140 "CRCW12063M92FKEA" 1206 537.5,506.25 r270 top value=3.92Meg
R141 "CRCW0603499KFKEA" 0603 1493.75,532.8 r90 top value=499k
R142 "Used in BOM report" 0805 1645.62,158.61 r270 top value=DNP
R143 "CRCW0805499KFKEA" 0805_HV 2475,279.04 r270 bottom value=499k
R144 "CRCW06030000Z0EA" 0603 1456.55,434.69 r180 top value=0
R145 "CRCW080510K0FKEA" 0805_HV 1608.12,284.69 r0 top value=10.0k
R146 "CRCW08050000Z0EA" 0805_HV 1870.62,278.44 r0 top value=0
R147 "CRCW06030000Z0EA" 0603 1139.37,390.94 r0 top value=0
R148 "CRCW0603100KFKEA" 0603 1426.87,328.69 r270 top value=100k
R149 "CRCW0603499KFKEA" 0603 1564.37,409.69 r90 top value=499k
R150 "CRCW0805402KFKEA" 0805_HV 920.62,340.94 r90 top value=402k
R151 "DNP" 0805 1462.5,172.79 r90 top
R152 "DNP" 0805 1375,212.5 r90 top
RF1 "CRCW25120000Z0EG" 2512 914.3,2875 r90 top value=0
RT1 "B57464S0509M000" S237 660.14,2930.7 r90 top value=5ohm
RT2 "NCP18WB473F10RB" 0603 272.54,4680.94 r90 bottom value=47.0k
RT100 "B57237S0259M00" S237 387.5,306.25 r90 top value="2.5 ohm"
RT101 "B57237S0259M00" S237 675,306.25 r90 top value="2.5 ohm"
T1 "750318431_R00" FP-750318431_R00_PTH_14-MFG 2860.14,4361.78 r0 top
TP1 "5000" Keystone5000 636.72,2525 r180 top
TP2 "5000" Keystone5000 150,2525 r270 top
TP3 "Suggest using a net name here" Keystone1503-2 4372.64,4555 r180 top
TP4 "Suggest using a net name here" Keystone1503-2 4372.64,4075.97 r180 top
TP5 "5000" Keystone5000 4435.14,4988.47 r270 top
TP6 "5000" Keystone5000 4435.14,5163.47 r270 top
TP7 "5001" Keystone5001 4333.77,5288.47 r270 top
TP100 "Suggest using a net name here" Keystone1503-2 131.25,131.25 r0 top
TP101 "5000" Keystone5000 350,675 r90 top
TP102 "Suggest using a net name here" Keystone1503-2 131.25,1650 r0 top
TP103 "5001" Keystone5001 2100,368.75 r90 top
TP104 "1508-0-57-15-00-00-03-0" Mill-Max_1508 1800,192.08 r90 top
U1 "UCC27712DR" D0008A_N 1585.14,4875.04 r270 bottom
U2 "UCC24612-1DBVR" DBV0005A_N 4197.64,3513.47 r270 bottom
U3 "UCC28780DR" D0016A_N 672.98,4872.34 r180 bottom
U4 "FOD817AS" N04C 2947.64,5163.47 r180 bottom
U5 "ATL431BQDBZR" DBZ0003A_N 3866.63,5229.53 r90 bottom
U100 "UCC28C42DR" D0008A_N 1606.82,557.8 r0 bottom
U101 "749251050" Wurth_WE-CST_EF5 1825.71,1308.43 r270 top value=500uH
U102 "TLV1805DBVR" DBV0006A_N 1301.87,347.19 r180 top

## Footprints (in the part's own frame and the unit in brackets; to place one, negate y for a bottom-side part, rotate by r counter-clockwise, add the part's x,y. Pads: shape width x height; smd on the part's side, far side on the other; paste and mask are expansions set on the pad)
0603 [mm] "0603 from SM-752 data"
  rect 1x0.95 smd: 1(-0.8,0) 2(0.8,0)
  silkscreen extent -1.52,-0.69 1.52,0.69, body extent -0.87,-0.47 0.87,0.47, height 1
0603_HV [mil] "Ernesto recommended land pattern.  26 mil between pads."
  rect 30x30 smd: 1(-28,0) 2(28,0)
  silkscreen extent -52,-24 52,24, body extent -34,-19 34,19, height 39
0805 [mm] "0805 from SM-752 data"
  rect 1.3x1.5 smd: 1(-0.85,0) 2(0.85,0)
  silkscreen extent -1.72,-0.97 1.72,0.97, body extent -1.1,-0.72 1.1,0.72, height 1.45
0805_HV [mil] "0805 with 30mil clearance between pads"
  rect 50x63 smd: 1(-40,0) 2(40,0)
  silkscreen extent -74,-40 74,40, body extent -43,-29 43,29, height 57
1206 [mm] "1206 from SM-752 data"
  rect 1.3x1.85 smd: 1(-1.45,0) 2(1.45,0)
  silkscreen extent -2.4,-1.21 2.4,1.21, body extent -1.7,-0.9 1.7,0.9, height 1.35
1206_180 [mm] "1206_180"
  rect 1.1x1.6 smd: 1(-1.7,0) 2(1.7,0)
  silkscreen extent -0.9,-1 0.9,1, body extent -1.75,-0.95 1.75,0.95, height 1.8
1206_190 [mm] "1206_190"
  rect 1.1x1.6 smd: 1(-1.7,0) 2(1.7,0)
  silkscreen extent -0.9,-1 0.9,1, body extent -1.75,-0.95 1.75,0.95, height 1.9
1210 [mm] "1210 from SM-752 data"
  rect 1.3x2.7 smd: 1(-1.45,0) 2(1.45,0)
  silkscreen extent -2.32,-1.57 2.32,1.57, body extent -1.7,-1.35 1.7,1.35, height 1.35
1210_270 [mm] "1210"
  rect 1.3x2.7 smd: 1(-1.45,0) 2(1.45,0)
  silkscreen extent -2.32,-1.57 2.32,1.57, body extent -1.7,-1.35 1.7,1.35, height 2.7
1210_280 [mm] "SMD, 2-Leads, Body 3.6x2.8mm, Height 2.8mm"
  rect 1.1x2.2 smd: 1(-1.65,0) 2(1.65,0)
  silkscreen extent -0.84,-1.4 0.84,1.4, body extent -1.8,-1.4 1.8,1.4, height 2.8
1812_254 [mm] "SMD, 2-Leads, Body 4.8x3.4mm"
  rect 1.6x3.4 smd: 1(-2,0) 2(2,0)
  silkscreen extent -0.8,-1.7 0.8,1.7, body extent -2.4,-1.7 2.4,1.7, height 2.54
2220 [mm] "Chip Capacitor, Body 5.7x5.0mm, IPC Medium Density"
  rect 1.6x5.3 smd: 1(-2.6,0) 2(2.6,0)
  silkscreen extent -3.69,-2.94 3.69,2.94, body extent -2.95,-2.62 2.95,2.62, height 1.35
2512 [mm] "Chip Resistor, Body 6.3x3.2mm, IPC Medium Density"
  rect 1.3x3.4 smd: 1(-2.95,0) 2(2.95,0)
  silkscreen extent -1.9,-1.6 1.9,1.6, body extent -3.22,-1.67 3.22,1.67, height 0.71
750318149 [mm] "TH, 12-Leads, Body 40.64x36.2mm"
  rrect50% 2.4x2.4 hole 1.6: 1(-17.5,15)
  round 2.4 hole 1.6: 2(-17.5,10) 3(-17.5,5) 4(-17.5,-5) 5(-17.5,-10) 6(-17.5,-15) 7(17.5,-15) 8(17.5,-10) 9(17.5,-5) 10(17.5,5) 11(17.5,10) 12(17.5,15)
  body extent -20.44,-18.1 20.2,18.1, height 38.1
CAPPR5-12.5x25 [mm] "Capacitor, Electrolytic, Radial; Body 12.5 x 25 mm (Dia.xH typ); Pin Spacing 5 mm (typ)"
  rect 1.5x1.5 hole 0.9: 1(-2.5,0)
  round 1.5 hole 0.9: 2(2.5,0)
  silkscreen extent -6.25,-6.25 6.25,6.25, body extent -6.25,-6.26 6.25,6.26, height 27
CAPPR7.5-16x31.5 [mm] "Capacitor, Electrolytic, Radial; Body 16 x 31.5 mm (Dia.xH typ); Pin Spacing 7.5 mm (typ)"
  rect 1.85x1.85 hole 1.1: 1(-3.75,0)
  round 1.85 hole 1.1: 2(3.75,0)
  silkscreen extent -8,-8 8,8, body extent -8,-8.01 8,8.01, height 33.5
CAPPR7.5-18x20 [mm] "Capacitor, Electrolytic, Radial; Body 18 x 20 mm (Dia.xH typ); Pin Spacing 7.5 mm (typ)"
  rect 1.85x1.85 hole 1.1: 1(-3.75,0)
  round 1.85 hole 1.1: 2(3.75,0)
  silkscreen extent -9,-9 9,9, body extent -9,-9.01 9,9.01, height 22
CAPPR7.5-18x31.5 [mm] "Capacitor, Electrolytic, Radial; Body 18 x 31.5 mm (Dia.xH typ); Pin Spacing 7.5 mm (typ)"
  rect 1.85x1.85 hole 1.1: 1(-3.75,0)
  round 1.85 hole 1.1: 2(3.75,0)
  silkscreen extent -9,-9 9,9, body extent -9,-9.01 9,9.01, height 33.5
CKG57N [mm] "Chip Capacitor, Body 6.0x5.0x5.0mm,"
  rect 2x5 smd: 1(-2.95,0) 2(2.95,0)
  silkscreen extent -3.2,-2.8 3.2,2.8, body extent -3.3,-2.75 3.3,2.75, height 5.5
D0008A_N [mm] "SOIC, 8-Leads, Body 4.9x3.9mm, Pitch 1.27mm, IPC Medium Density"
  oval 1.45x0.6 smd: 1(-2.725,1.905) 2(-2.725,0.635) 3(-2.725,-0.635) 4(-2.725,-1.905) 5(2.725,-1.905) 6(2.725,-0.635) 7(2.725,0.635) 8(2.725,1.905)
  silkscreen extent -3.3,-2.5 0.9,2.5, body extent -3,-2.45 3,2.45, height 1.63
D0016A_N [mm] "SOIC, 16-Leads, Body 9.9x3.9mm, Pitch 1.27mm, IPC Medium Density"
  oval 1.45x0.6 smd: 1(-2.725,4.445) 2(-2.725,3.175) 3(-2.725,1.905) 4(-2.725,0.635) 5(-2.725,-0.635) 6(-2.725,-1.905) 7(-2.725,-3.175) 8(-2.725,-4.445) 9(2.725,-4.445) 10(2.725,-3.175) 11(2.725,-1.905) 12(2.725,-0.635) 13(2.725,0.635) 14(2.725,1.905) 15(2.725,3.175) 16(2.725,4.445)
  silkscreen extent -3.3,-5 0.9,5, body extent -3,-4.95 3,4.95, height 1.6
DBV0005A_N [mm] "SOT23, 5-Leads, Body 2.9x1.6mm, Pitch 0.95mm, Lead Span 2.8mm, IPC Medium Density"
  rrect17% 1x0.6 smd: 1(-1.375,0.95) 2(-1.375,0) 3(-1.375,-0.95) 4(1.375,-0.95) 5(1.375,0.95)
  silkscreen extent -0.25,-1.55 0.25,1.55, body extent -1.42,-1.46 1.42,1.46, height 1.09
DBV0006A_N [mm] "SOT23, 6-Leads, Body 2.9x1.6mm, Pitch 0.95mm, Lead Span 2.8mm, IPC Medium Density"
  rrect17% 1x0.6 smd: 1(-1.375,0.95) 2(-1.375,0) 3(-1.375,-0.95) 4(1.375,-0.95) 5(1.375,0) 6(1.375,0.95)
  silkscreen extent -1.68,-1.55 0.5,1.55, body extent -1.42,-1.46 1.42,1.46, height 1.12
DBZ0003A_N [mm] "SOT23, 3-Leads, Body 2.9x1.3mm, Pitch 0.95mm, Lead Span 2.4mm, IPC Medium Density"
  rrect17% 1x0.6 smd: 1(-1.2,0.95) 2(-1.2,-0.95) 3(1.2,0)
  silkscreen extent 0.2,-1.5 0.7,1.5, body extent -1.26,-1.46 1.26,1.46, height 0.98
EE_1800x2000 [mm] "PANASONIC"
  rect 1.75x1.75 hole 1.1: 1(-3.75,0)
  round 1.75 hole 1.1: 2(3.75,0)
  silkscreen extent -9.3,-9.3 9.3,9.3, body extent -9.18,-9.23 9.22,9.24, height 22.01
FP-750318431_R00_PTH_14-MFG [mm]
  rrect5% 2.02x2.02 hole 1.32 paste-1000 mask+0: 1(-12.7,11.43)
  round 2.02 hole 1.32 paste-1000 mask+0: 2(-12.7,7.62) 3(-12.7,3.81) 4(-12.7,0) 5(-12.7,-3.81) 6(-12.7,-7.62) 7(-12.7,-11.43) 8(12.7,-11.43) 9(12.7,-7.62) 10(12.7,-3.81) 11(12.7,0) 12(12.7,3.81) 13(12.7,7.62) 14(12.7,11.43)
  body extent -16.22,-13.62 16.22,13.62, height 0.25
FUSE_0443 [mm] "LITTELFUSE"
  rect 3.25x3.43 smd: 1(-4.675,0) 2(4.675,0)
  silkscreen extent -2.7,-1.7 2.7,1.7, body extent -5.05,-1.56 5.05,1.56, height 3.12
HSINK_531002B02500G [mm] "TH, 2-Leads, Body 34.92x12.7mm, Pin Spacing 25.4mm"
  round 3.2 hole 2.67: 1(-12.7,0) 2(12.7,0)
  silkscreen extent -17.46,-6.35 17.46,6.35, body extent -17.46,-6.35 17.46,6.35, height 25.4
HSINK_FA-T220-64E [mm] "TH, 2-Leads, Body 41.6x25mm, Pin Spacing 25.4mm"
  round 3.4 hole 2.55: 1(-12.7,0) 2(12.7,0)
  silkscreen extent -20.8,-12.56 20.8,12.57, body extent -20.82,-12.57 20.78,12.57, height 63.5
IEC_HighVoltage_Medium [mil]
  silkscreen extent -217,-176 217,200
IEC_HighVoltage_Small [mil]
  silkscreen extent -107,-88 107,97
Keystone1503-2 [mm] "Double Turret"
  round 5.1 hole 3.1: 1(0,0)
  silkscreen extent -2.79,-2.79 2.79,2.79, body extent -2.4,-2.4 2.38,2.4, height 9.22
Keystone5000 [mil] "For Keystone 500x miniature loop terminals"
  round 80 hole 40: 1(0,0)
  silkscreen extent -52,-52 52,52, body extent -49,-49 49,49, height 182
Keystone5001 [mil] "For Keystone 500x miniature loop terminals"
  round 80 hole 40: 1(0,0)
  silkscreen extent -52,-52 52,52, body extent -49,-49 49,49, height 182
KX_1000x700 [mm] "TH, 2-Leads, Dia 10mm, Lead Spacing 10mm"
  round 1.4 hole 0.9: 1(-5,0) 2(5,0)
  silkscreen extent -5,-3.5 5,3.5, body extent -5.32,-3.5 5.33,3.5, height 13
Mill-Max_1508 [mil] "Testpoint, SMT"
  round 110 smd: 1(0,0)
  body extent -51,-51 51,51, height 175
N04C [mm] "FAIRCHILD"
  rect 1.3x1.5 smd mask+0.065: 1(-4.587,1.27) 2(-4.612,-1.27) 3(4.588,-1.27) 4(4.613,1.27)
  silkscreen extent -3.56,-2.3 3.56,2.72, body extent -5.08,-2.3 5.08,2.29, height 3.87
Panasonic_1250x3000 [mm] "TH, 2-Leads, Dia 12.5mm, Lead Sapcing 5mm"
  rrect50% 1.65x1.65 hole 1.1: 1(-2.5,0)
  round 1.65 hole 1.1: 2(2.5,0)
  body extent -6.5,-6.5 6.51,6.5, height 32.01
PG-TDSON-8 [mm] "Infineon recommended land pattern"
  rect 1.2x0.65 smd: 1(-2.825,1.905) 2(-2.825,0.635) 3(-2.825,-0.635) 4(-2.825,-1.905)
  rect 0.5x0.7 smd: 5(3.175,-2) 6(3.175,-0.675) 7(3.175,0.675) 8(3.175,2)
  rect 4.5x4.7 smd paste-2.25: 9(0.675,0)
  silkscreen extent -3.74,-3 3.74,3, body extent -3.18,-2.89 3.18,2.9, height 1.1
S237 [mm] "EPCOS"
  round 1.75 hole 1.1: 1(-3.75,0) 2(3.75,0)
  silkscreen extent -7.5,-3.5 7.5,3.5, body extent -7.47,-3.5 7.47,3.5, height 21.99
SM_RADIAL_D8 [mm] "6.3 x 7.7mm:  Panasonic D8"
  rect 3.2x1.6 smd: 1(-2.5,0) 2(2.5,0)
  silkscreen extent -3.4,-3.4 3.4,3.4, body extent -3.4,-3.4 3.4,3.4, height 8.01
SMA [mm] "Molded Diode, 2-Leads, Body 4.3x2.6mm, IPC Medium Density, based on OnSemi component dimensions and land pattern"
  rect 2x2 smd: 1(-2,0) 2(2,0)
  silkscreen extent -3.66,-1.57 2.79,1.57, body extent -2.6,-1.3 2.6,1.3, height 2.42
SMC [mil] "Molded Diode, 2-Leads, Body 6.9x5.8mm, IPC Medium Density, based on OnSemi component dimensions and land patterns"
  rect 110x150 smd: 1(-140.49,0) 2(140.49,0)
  silkscreen extent -221,-123 189,124, body extent -156,-116 156,116, height 91
SOD-123 [mm] "On Semi recommended land pattern"
  rect 0.915x1.22 smd: 1(-1.637,0) 2(1.637,0)
  silkscreen extent -2.74,-1.17 2.03,1.17, body extent -1.93,-0.9 1.93,0.9, height 1.35
SOD-323 [mm] "NXP recommended land pattern"
  rect 0.6x0.6 smd paste-0.05: 1(-1.1,0) 2(1.1,0)
  silkscreen extent -2.06,-0.86 1.53,0.86, body extent -1.3,-0.67 1.3,0.68, height 1.1
SOT-23 [mm] "SOT23, 3-Leads, Body 2.9x1.3mm, Pitch 0.95mm, Lead Span 2.5mm, IPC Medium Density"
  rrect50% 1x0.6 smd: 1(-1.2,0.95) 2(-1.2,-0.95) 3(1.2,0)
  silkscreen extent -1.62,-1.5 0.7,1.5, body extent -1.16,-1.45 1.21,1.45, height 1
SOT-223 [mm] "SOT223/SC73, 4-Leads, Body 6.5x3.5mm, Pitch 2.3mm, Lead Span 7mm, IPC Medium Density"
  rrect10% 2.4x1 smd: 1(-2.9,2.3) 2(-2.9,0) 3(-2.9,-2.3)
  rrect4% 2.4x3.3 smd: 4(2.9,0)
  silkscreen extent -3.32,-3.35 1.4,3.35, body extent -3.5,-3.25 3.5,3.25, height 1.62
TO-220-2 [mm] "CREE"
  rrect50% 1.9x1.9 hole 1.4: 1(-2.54,0)
  round 1.9 hole 1.4: 2(2.54,0)
  silkscreen extent -5.25,-1.64 5.26,3.01, body extent -5.21,-1.57 5.21,3.12, height 19.47
TO-220AB [mil] "Copied from Altium's version of TO3B"
  rrect25% 76x118.11 hole 50: 1(-100,0)
  oval 76x118.11 hole 50: 2(0,0) 3(100,0)
  silkscreen extent -221,-59 221,126, body extent -221,-59 221,126, height 765
WE-TI_5075 [mm] "Wurth WE-TI 5075"
  rect 1.4x1.4 hole 0.787: 1(-1.25,0)
  round 1.4 hole 0.787: 2(1.25,0)
  silkscreen extent -3,-3 3,3, body extent -3,-3 3,3, height 8.5
Wurth_WE-CST_EF5 [mm] "SMD, 8-Leads, Body 5.6x5.6mm"
  rrect8% 1.6x1.2 smd: 1(-3.6,1.85) 2(-3.6,0) 3(-3.6,-1.85) 4(3.6,-1.85) 5(3.6,0) 6(3.6,1.85)
  rrect4% 3x2.5 smd: 7(0,-2.6) 8(0,2.6)
  body extent -3.85,-3.45 3.85,3.45, height 5.33

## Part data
C1 C2: library part Capacitor_Polarized, "CAP, [Technology], 82uF, 450V, +/-xx%, xxOhm ESR, [MountType]", Alternate Manufacturer=-, Manufacturer="Used in BOM report", Voltage=450V
C3: "CAP, CERM, 0.47 µF, 500 V,+/- 10%, X7R, 1812", Cap_Case=1812, Manufacturer="Knowles Capacitors", Supplier Part Number 1=1608-1155-1-ND, TempCo=X7R, Tolerance_%=10, Value2=500V, ValueDisplayed=0.47µF
C4: library part CMP-0008727-1, "CAP, CERM, 0.1 uF, 450 V, +/- 10%, X7T, 1206_190", Cap_Case=1206, Manufacturer=TDK, Supplier Part Number 1=445-7758-1-ND, TempCo=X7T, Tolerance_%=10%, Value1=Unknown, Value2=450V, ValueDisplayed=0.1uF
C5: "CAP, CERM, 0.47 µF, 250 V,+/- 10%, X7R, 2220", Cap_Case=2220, Manufacturer=MuRata, Supplier Part Number 1=490-3548-1-ND, TempCo=X7R, Tolerance_%=10, Value2=250V, ValueDisplayed=0.47µF
C6: library part GRM55DR72E474KW01L, "CAP, CERM, 0.68 µF, 250 V,+/- 10%, X7R, 2220", Cap_Case=2220, Manufacturer=MuRata, Supplier Part Number 1=GRM55DR72E684KW01L, TempCo=X7R, Tolerance_%=10, Value2=250V, ValueDisplayed=0.68uF
C7: library part GRM55DR72E474KW01L, "CAP, CERM, 0.68 µF, 250 V,+/- 10%, X7R, 2220", Cap_Case=2220, Manufacturer=MuRata, TempCo=X7R, Tolerance_%=10, Value2=250V, ValueDisplayed=DNP
C8: "CAP, CERM, 0.15 µF, 50 V,+/- 10%, X7R, 0805", Cap_Case=0805, Manufacturer=Kemet, Supplier Part Number 1=399-3489-1-ND, TempCo=X7R, Tolerance_%=10, Value1="0.054 ohm", Value2=50V, ValueDisplayed=0.15µF
C9 C25: "CAP, CERM, 1 µF, 50 V,+/- 10%, X7R, 0805", Cap_Case=0805, Manufacturer=MuRata, Supplier Part Number 1=490-4736-1-ND, TempCo=X7R, Tolerance_%=10, Value2=50V, ValueDisplayed=1µF
C10 C31 C34: "CAP, CERM, 0.1 µF, 50 V,+/- 10%, X7R, 0805", Cap_Case=0805, Manufacturer=MuRata, Supplier Part Number 1=490-1666-1-ND, TempCo=X7R, Tolerance_%=10, Value2=50V, ValueDisplayed=0.1µF
C11 C12: "CAP, CERM, 33 pF, 50 V,+/- 5%, C0G/NP0, 0603", Cap_Case=0603, Manufacturer=MuRata, Supplier Part Number 1=490-1415-1-ND, TempCo=C0G/NP0, Tolerance_%=5, Value2=50V, ValueDisplayed=33pF
C13: library part CMP-0079558-1, "CAP, AL, 1200 µF, 35 V, +/- 20%, TH", Cap_Case=12.5x30mm, Manufacturer=Panasonic, Tolerance_%=20%, Value2=35V, ValueDisplayed=1200µF
C14 C100: library part Capacitor_Polarized, "CAP, [Technology], xxxF, xxV, +/-xx%, xxOhm ESR, [MountType]", Alternate Manufacturer=-, Manufacturer="Used in BOM report"
C15: "CAP, CERM, 10 µF, 50 V,+/- 10%, X7R, 1210", Cap_Case=1210, Manufacturer=MuRata, Supplier Part Number 1=490-6544-1-ND, TempCo=X7R, Tolerance_%=10, Value2=50V, ValueDisplayed=10µF
C16: "CAP, CERM, 1500 pF, 630 V,+/- 10%, X7R, 1206", Cap_Case=1206, Manufacturer=MuRata, Supplier Part Number 1=490-3507-1-ND, TempCo=X7R, Tolerance_%=10, Value2=630V, ValueDisplayed=1500pF
C17 C117 C118 C119 C123: "CAP, CERM, 1 µF, 50 V,+/- 10%, X7R, 1206", Cap_Case=1206, Manufacturer=MuRata, Supplier Part Number 1=GRM31MR71H105KA88L-ND, TempCo=X7R, Tolerance_%=10, Value2=50V, ValueDisplayed=1µF
C18: "CAP, CERM, 1.5 µF, 50 V,+/- 10%, X7R, 1206", Cap_Case=1206, Manufacturer=TDK, Supplier Part Number 1=445-7695-1-ND, TempCo=X7R, Tolerance_%=10, Value1="0.007741 ohm", Value2=50V, ValueDisplayed=1.5µF
C19 C20: "CAP, CERM, 10 µF, 50 V,+/- 20%, X7R, 1210", Cap_Case=1210, Manufacturer=TDK, Supplier Part Number 1=445-14933-1-ND, TempCo=X7R, Tolerance_%=20, Value2=50V, ValueDisplayed=10µF
C21: library part DE1E3KX332MN4AP01F, "CAP, CERM, 3300 pF, X1 250 VAC/Y1 300 VAC, +/- 20%, E, D10xT7mm", Cap_Case=10x7mm, Manufacturer=MuRata, Supplier Part Number 1=490-9516-1-ND, TempCo=E, Tolerance_%=20
C22: "CAP, CERM, 3300 pF, X1 250 VAC/Y1 300 VAC, +/- 20%, E, D10xT7mm", Cap_Case=10x7mm, Manufacturer=MuRata, Supplier Part Number 1=490-9516-1-ND, TempCo=E, Tolerance_%=20, ValueDisplayed=3300pF
C23 C30: "CAP, CERM, 3.3 pF, 50 V,+/- 8%, C0G/NP0, 0603", Cap_Case=0603, Manufacturer=AVX, Supplier Part Number 1=478-1157-1-ND, TempCo=C0G/NP0, Tolerance_%=8, Value1="0.792 ohm", Value2=50V, ValueDisplayed=3.3pF
C24: "CAP, CERM, 2.2 µF, 50 V,+/- 10%, X7R, 0805", Cap_Case=0805, Manufacturer=TDK, Supplier Part Number 1=445-5968-1-ND, TempCo=X7R, Tolerance_%=10, Value1="0.00366 ohm", Value2=50V, ValueDisplayed=2.2µF
C26 C115 C122: "CAP, CERM, 100 pF, 50 V,+/- 5%, C0G/NP0, 0603", Cap_Case=0603, Manufacturer=MuRata, Supplier Part Number 1=490-1427-1-ND, TempCo=C0G/NP0, Tolerance_%=5, Value2=50V, ValueDisplayed=100pF
C27: "CAP, CERM, 2200 pF, 50 V,+/- 10%, X7R, 0603", Cap_Case=0603, Manufacturer=MuRata, Supplier Part Number 1=490-1500-1-ND, TempCo=X7R, Tolerance_%=10, Value2=50V, ValueDisplayed=2200pF
C28 C29: "CAP, CERM, 0.015 µF, 50 V,+/- 10%, X7R, 0603", Cap_Case=0603, Manufacturer=MuRata, Supplier Part Number 1=490-1514-1-ND, TempCo=X7R, Tolerance_%=10, Value2=50V, ValueDisplayed=0.015µF
C32: "CAP, AL, 100 µF, 35 V, +/- 20%, 0.34 ohm, AEC-Q200 Grade 2, SMD", Cap_Case=D8, Manufacturer=Panasonic, Supplier Part Number 1=PCE3836CT-ND, Tolerance_%=20, Value1="0.34 ohm", Value2=35V, ValueDisplayed=100µF
C33: "CAP, CERM, 3300 pF, 50 V,+/- 10%, X7R, 0603", Cap_Case=0603, Manufacturer=MuRata, Supplier Part Number 1=490-1503-1-ND, TempCo=X7R, Tolerance_%=10, Value2=50V, ValueDisplayed=3300pF
C35: "CAP, CERM, 10 µF, 50 V,+/- 20%, X7R, 1210", Cap_Case=1210, Manufacturer=MuRata, Supplier Part Number 1=490-12775-1-ND, TempCo=X7R, Tolerance_%=20, Value2=50V, ValueDisplayed=10µF
C36 C38: "CAP, CERM, 27 pF, 50 V,+/- 5%, C0G/NP0, 0603", Cap_Case=0603, Manufacturer=MuRata, Supplier Part Number 1=490-1413-1-ND, TempCo=C0G/NP0, Tolerance_%=5, Value2=50V, ValueDisplayed=27pF
C37: "CAP, CERM, 180 pF, 50 V,+/- 5%, C0G/NP0, 0805", Cap_Case=0805, Manufacturer=MuRata, Supplier Part Number 1=GRM2165C1H181JA01D-ND, TempCo=C0G/NP0, Tolerance_%=5, Value2=50V, ValueDisplayed=180pF
C39: "CAP, CERM, 2.2 µF, 50 V,+/- 10%, X7R, 1206", Cap_Case=1206, Manufacturer=MuRata, Supplier Part Number 1=490-3367-1-ND, TempCo=X7R, Tolerance_%=10, Value2=50V, ValueDisplayed=2.2µF
C101: library part Capacitor_Polarized, "CAP, [Technology], 47uF, 450V, +/-xx%, xxOhm ESR, [MountType]", Alternate Manufacturer=-, Manufacturer=Nichicon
